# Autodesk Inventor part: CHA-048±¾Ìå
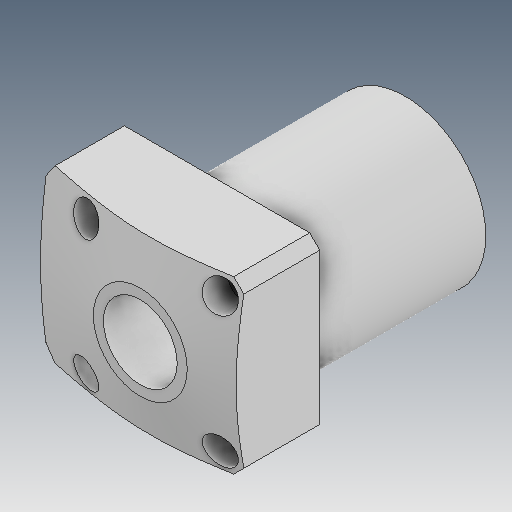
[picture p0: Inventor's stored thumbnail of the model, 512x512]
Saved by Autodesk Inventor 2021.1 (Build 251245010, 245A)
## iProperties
Created: 2019-05
Part Number: CHA-048±¾Ìå
Material: Ogólny
Document SubType Name: Modeling
Designer: user
Density: 1 g/cm^3
Appearance: Domyślna
Author: user
Revision Number: ÈÎºÎ
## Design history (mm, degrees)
feature "ÊäÈë1"
node "Bryła1"
